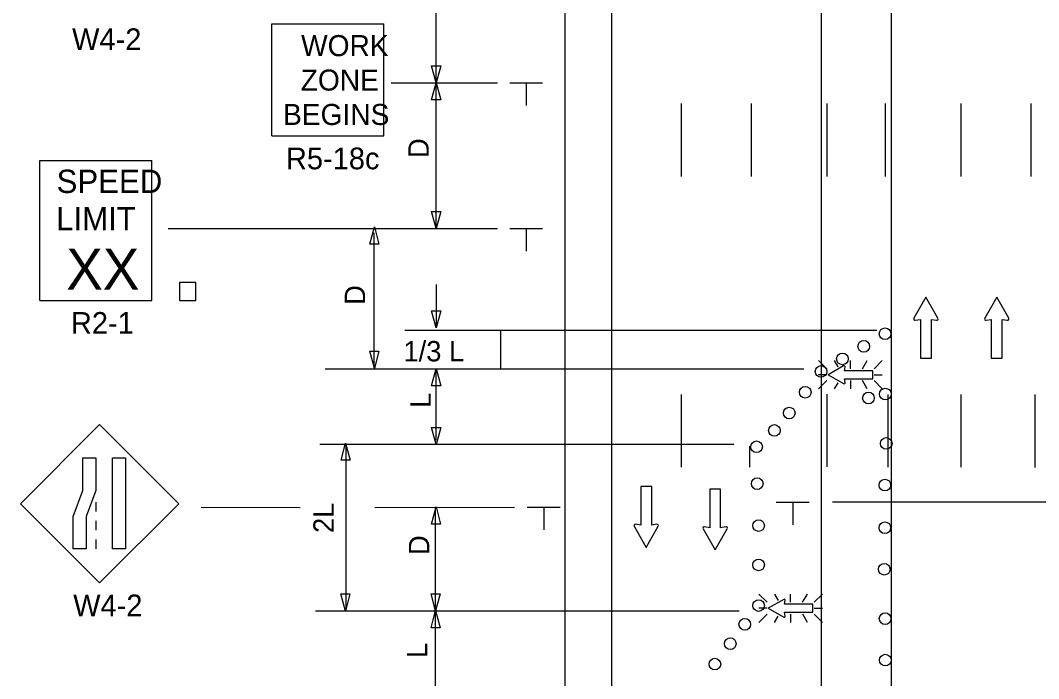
# Model space of a CAD drawing. Extents: x 16646 to 19498, y 2812 to 4437.
# Drawn here: x 16735.8 to 17085.1, y 3563.2 to 3789.1 of the extents above; entities that cross this region are included whole.
import ezdxf

# ---------------------------------------------------------------- set-up
doc = ezdxf.new("R2010")
doc.units = 0
for name, color, linetype in [('ALI_LEGAL_EX', 7, 'Continuous'), ('MT_SCRATCH_LEVEL_E', 7, 'Continuous'), ('PAVT_EDGE_EX', 7, 'Continuous'), ('TRAFFIC_SIGNS_PR', 7, 'Continuous'), ('TYPICAL_EX', 7, 'Continuous'), ('TYPICAL_TEXT_DIMEN_PR', 7, 'Continuous')]:
    doc.layers.add(name, color=color, linetype=linetype)

msp = doc.modelspace()

# ---------------------------------------------------------------- linework, layer by layer
at = {"layer": 'ALI_LEGAL_EX'}
for points in [[(16962.57, 3735.48), (16962.57, 3760.48)], [(16986.57, 3735.48), (16986.57, 3760.48)], [(17012.57, 3735.48), (17012.57, 3760.48)], [(17032.57, 3735.48), (17032.57, 3760.48)], [(17058.57, 3735.48), (17058.57, 3760.48)], [(17082.57, 3735.48), (17082.57, 3760.48)], [(16962.57, 3635.73), (16962.57, 3660.73)], [(17012.57, 3635.86), (17012.57, 3660.86)], [(17033.51, 3635.73), (17033.51, 3660.69)], [(17058.57, 3635.73), (17058.57, 3660.69)], [(17083.89, 3635.68), (17083.89, 3660.68)], [(16986.04, 3635.73), (16986.04, 3642.97)]]:
    msp.add_lwpolyline(points, dxfattribs=at)
at = {"layer": 'MT_SCRATCH_LEVEL_E'}
for p, q in [((17046.44, 3694.1), (17042.33, 3686.86)), ((17046.44, 3694.1), (17042.33, 3686.86)), ((17050.58, 3686.86), (17046.44, 3694.1)), ((17050.58, 3686.86), (17046.44, 3694.1)), ((17070.71, 3694.1), (17066.6, 3686.86)), ((17070.71, 3694.1), (17066.6, 3686.86)), ((17074.85, 3686.86), (17070.71, 3694.1)), ((17074.85, 3686.86), (17070.71, 3694.1)), ((17042.81, 3686.18), (17044.59, 3686.49)), ((17042.81, 3686.18), (17044.59, 3686.49)), ((17044.59, 3686.49), (17044.59, 3673.23)), ((17044.59, 3686.49), (17044.59, 3673.23)), ((17048.33, 3673.23), (17048.33, 3686.49)), ((17048.33, 3686.49), (17050.11, 3686.18)), ((17048.33, 3673.23), (17048.33, 3686.49)), ((17048.33, 3686.49), (17050.11, 3686.18)), ((17067.08, 3686.18), (17068.85, 3686.49)), ((17067.08, 3686.18), (17068.85, 3686.49)), ((17068.85, 3686.49), (17068.85, 3673.23)), ((17068.85, 3686.49), (17068.85, 3673.23)), ((17072.6, 3673.23), (17072.6, 3686.49)), ((17072.6, 3686.49), (17074.38, 3686.18)), ((17072.6, 3673.23), (17072.6, 3686.49)), ((17072.6, 3686.49), (17074.38, 3686.18)), ((17044.59, 3673.23), (17048.33, 3673.23)), ((17044.59, 3673.23), (17048.33, 3673.23)), ((17068.85, 3673.23), (17072.6, 3673.23)), ((17068.85, 3673.23), (17072.6, 3673.23)), ((16952.39, 3629.12), (16948.64, 3629.12)), ((16948.64, 3629.12), (16948.64, 3615.86)), ((16952.39, 3629.12), (16948.64, 3629.12)), ((16948.64, 3629.12), (16948.64, 3615.86)), ((16952.39, 3615.86), (16952.39, 3629.12)), ((16952.39, 3615.86), (16952.39, 3629.12)), ((16976.02, 3628.29), (16972.28, 3628.29)), ((16972.28, 3628.29), (16972.28, 3615.03)), ((16976.02, 3628.29), (16972.28, 3628.29)), ((16972.28, 3628.29), (16972.28, 3615.03)), ((16976.02, 3615.03), (16976.02, 3628.29)), ((16976.02, 3615.03), (16976.02, 3628.29)), ((16946.39, 3615.49), (16950.53, 3608.25)), ((16946.39, 3615.49), (16950.53, 3608.25)), ((16948.64, 3615.86), (16946.87, 3616.18)), ((16948.64, 3615.86), (16946.87, 3616.18)), ((16950.53, 3608.25), (16954.65, 3615.49)), ((16950.53, 3608.25), (16954.65, 3615.49)), ((16954.16, 3616.18), (16952.39, 3615.86)), ((16954.16, 3616.18), (16952.39, 3615.86)), ((16972.28, 3615.03), (16970.5, 3615.35)), ((16972.28, 3615.03), (16970.5, 3615.35)), ((16977.8, 3615.35), (16976.02, 3615.03)), ((16977.8, 3615.35), (16976.02, 3615.03)), ((16970.02, 3614.66), (16974.17, 3607.43)), ((16970.02, 3614.66), (16974.17, 3607.43)), ((16974.17, 3607.43), (16978.28, 3614.66)), ((16974.17, 3607.43), (16978.28, 3614.66))]:
    msp.add_line(p, q, dxfattribs=at)
for centre, start, end in [((17042.73, 3686.63), 150.4248, 279.9638), ((17042.73, 3686.63), 150.4248, 279.9638), ((17050.18, 3686.64), 260.0362, 29.7731), ((17050.18, 3686.64), 260.0362, 29.7731), ((17067, 3686.63), 150.4248, 279.9638), ((17067, 3686.63), 150.4248, 279.9638), ((17074.44, 3686.64), 260.0362, 29.7731), ((17074.44, 3686.64), 260.0362, 29.7731), ((16946.8, 3615.72), 80.0362, 209.7731), ((16946.8, 3615.72), 80.0362, 209.7731), ((16954.24, 3615.72), 330.4248, 99.9638), ((16954.24, 3615.72), 330.4248, 99.9638), ((16970.43, 3614.89), 80.0362, 209.7731), ((16970.43, 3614.89), 80.0362, 209.7731), ((16977.87, 3614.89), 330.4248, 99.9638), ((16977.87, 3614.89), 330.4248, 99.9638)]:
    msp.add_arc(centre, 0.463, start, end, dxfattribs=at)
at = {"layer": 'PAVT_EDGE_EX'}
for p, q in [((16938.57, 3998.47), (16938.57, 3231.86)), ((17010.57, 3998.47), (17010.57, 3554.03)), ((17034.57, 3998.47), (17034.57, 3594.25)), ((16922.57, 3836.4), (16922.57, 3233.74)), ((17010.57, 3836.4), (17010.57, 3563.39)), ((17034.57, 3836.4), (17034.57, 3553.74))]:
    msp.add_line(p, q, dxfattribs=at)
at = {"layer": 'TRAFFIC_SIGNS_PR'}
for p, q in [((16822.13, 3749.41), (16822.13, 3787.81)), ((16822.13, 3787.81), (16860.53, 3787.81)), ((16860.53, 3749.41), (16860.53, 3787.81)), ((16822.13, 3749.41), (16860.53, 3749.41)), ((16742.5, 3740.98), (16780.9, 3740.98)), ((16742.5, 3692.98), (16742.5, 3740.98)), ((16780.9, 3692.98), (16780.9, 3740.98)), ((16742.5, 3692.98), (16780.9, 3692.98)), ((17009.65, 3672.35), (17012.47, 3669.53)), ((17016.37, 3670.16), (17015.11, 3672.35)), ((17020.56, 3669.53), (17020.56, 3672.35)), ((17024.69, 3669.53), (17026.32, 3672.35)), ((17028.64, 3669.53), (17031.46, 3672.35)), ((17012.47, 3667.5), (17009.65, 3667.5)), ((17028.64, 3667.5), (17031.46, 3667.5)), ((17009.65, 3662.65), (17012.47, 3665.47)), ((17015.09, 3662.64), (17016.29, 3664.74)), ((17020.56, 3665.47), (17020.56, 3662.64)), ((17026.34, 3662.64), (17024.72, 3665.47)), ((17028.64, 3665.47), (17031.46, 3662.64)), ((16763, 3650.39), (16735.84, 3623.23)), ((16790.15, 3623.23), (16763, 3650.39)), ((16735.84, 3623.23), (16763, 3596.08)), ((16761.75, 3623.73), (16761.75, 3620.53)), ((16763, 3596.08), (16790.15, 3623.23)), ((16761.75, 3617.33), (16761.75, 3614.13)), ((16761.75, 3610.93), (16761.75, 3607.73)), ((16989.12, 3592.24), (16991.94, 3589.43)), ((16995.84, 3590.06), (16994.58, 3592.25)), ((17000.03, 3589.43), (17000.03, 3592.25)), ((17004.16, 3589.43), (17005.79, 3592.25)), ((17008.11, 3589.43), (17010.93, 3592.25)), ((16991.94, 3587.39), (16989.12, 3587.39)), ((17008.11, 3587.39), (17010.93, 3587.39)), ((16989.12, 3582.54), (16991.94, 3585.36)), ((16994.56, 3582.54), (16995.77, 3584.64)), ((17000.03, 3585.36), (17000.03, 3582.54)), ((17005.82, 3582.54), (17004.19, 3585.36)), ((17008.11, 3585.36), (17010.93, 3582.54))]:
    msp.add_line(p, q, dxfattribs=at)
for points in [[(16790.48, 3692.98), (16796.07, 3692.98), (16796.07, 3699.15), (16790.48, 3699.15)], [(16761.75, 3638.97), (16761.75, 3627.79), (16758.41, 3618.91), (16758.41, 3607.73), (16753.91, 3607.73), (16753.91, 3618.91), (16757.26, 3627.79), (16757.26, 3638.97)], [(16771.89, 3638.97), (16771.89, 3607.73), (16767.39, 3607.73), (16767.39, 3638.97)]]:
    msp.add_lwpolyline(points, close=True, dxfattribs=at)
for points in [[(17018.23, 3670.51), (17012.92, 3667.5), (17018.23, 3664.46)], [(17018.73, 3664.82), (17018.5, 3666.11), (17028.22, 3666.11), (17028.22, 3668.86), (17018.5, 3668.86), (17018.73, 3670.16)], [(16997.7, 3590.41), (16992.39, 3587.39), (16997.7, 3584.35)], [(16998.2, 3584.71), (16997.97, 3586.01), (17007.69, 3586.01), (17007.69, 3588.75), (16997.97, 3588.75), (16998.2, 3590.06)]]:
    msp.add_lwpolyline(points, dxfattribs=at)
for centre in [(17032.45, 3681.54), (17032.45, 3681.54), (17025.13, 3677.23), (17017.8, 3672.92), (17010.47, 3668.61), (17005.05, 3661.48), (17026.74, 3659.51), (17032.51, 3660.87), (16999.56, 3654.35), (16994.47, 3648.37), (16988.36, 3642.77), (17032.81, 3643.91), (16988.57, 3630.13), (17032.38, 3629.64), (16989.06, 3615.74), (16989.06, 3615.74), (17032.38, 3615), (16989.06, 3602.26), (17032.16, 3600.77), (16989.06, 3588.33), (16984.33, 3581.88), (17032.46, 3583.82), (16979.34, 3575.24), (16974.05, 3568.22), (17032.52, 3569.59)]:
    msp.add_circle(centre, 2, dxfattribs=at)
for centre, start, end in [((17018.39, 3670.21), 350.7308, 118.8916), ((17018.39, 3664.76), 241.4833, 9.9593), ((16997.87, 3590.11), 350.7308, 118.8916), ((16997.86, 3584.65), 241.4833, 9.9593)]:
    msp.add_arc(centre, 0.341, start, end, dxfattribs=at)
at = {"layer": 'TYPICAL_EX'}
msp.add_line((16922.57, 3998.47), (16922.57, 3232.23), dxfattribs=at)
at = {"layer": 'TYPICAL_TEXT_DIMEN_PR'}
for p, q in [((16878.47, 3767.62), (16878.47, 3817.62)), ((16878.47, 3767.62), (16876.9, 3773.48)), ((16876.9, 3773.48), (16878.47, 3773.48)), ((16878.47, 3773.48), (16880.04, 3773.48)), ((16880.04, 3773.48), (16878.47, 3767.62)), ((16863.04, 3767.62), (16899.47, 3767.62)), ((16873.47, 3767.62), (16899.47, 3767.62)), ((16876.9, 3761.75), (16878.47, 3767.62)), ((16878.47, 3767.62), (16880.04, 3761.75)), ((16878.47, 3717.62), (16878.47, 3767.62)), ((16903.72, 3767.62), (16914.97, 3767.62)), ((16909.35, 3767.62), (16909.35, 3759.83)), ((16878.47, 3761.75), (16876.9, 3761.75)), ((16880.04, 3761.75), (16878.47, 3761.75)), ((16878.47, 3717.62), (16876.9, 3723.48)), ((16876.9, 3723.48), (16878.47, 3723.48)), ((16878.47, 3723.48), (16880.04, 3723.48)), ((16880.04, 3723.48), (16878.47, 3717.62)), ((16786.55, 3717.62), (16899.47, 3717.62)), ((16855.69, 3712.33), (16857.26, 3718.19)), ((16857.25, 3669.84), (16857.25, 3716.17)), ((16857.26, 3718.19), (16858.83, 3712.33)), ((16903.72, 3717.62), (16914.97, 3717.62)), ((16909.35, 3717.62), (16909.35, 3709.83)), ((16857.26, 3712.33), (16855.69, 3712.33)), ((16858.83, 3712.33), (16857.26, 3712.33)), ((16878.47, 3698.46), (16878.47, 3683.54)), ((16878.47, 3683.54), (16876.9, 3689.4)), ((16876.9, 3689.4), (16878.47, 3689.4)), ((16878.47, 3689.4), (16880.04, 3689.4)), ((16880.04, 3689.4), (16878.47, 3683.54)), ((16867.72, 3682.77), (17029.62, 3682.77)), ((16900.58, 3682.68), (16900.58, 3669.68)), ((16857.26, 3669.72), (16855.69, 3675.59)), ((16855.69, 3675.59), (16857.26, 3675.59)), ((16857.26, 3675.59), (16858.83, 3675.59)), ((16858.83, 3675.59), (16857.26, 3669.72)), ((16840.41, 3669.53), (17004.53, 3669.53)), ((16876.9, 3663.72), (16878.47, 3669.58)), ((16878.47, 3669.58), (16880.04, 3663.72)), ((16878.47, 3645.04), (16878.47, 3669.15)), ((16878.47, 3663.72), (16876.9, 3663.72)), ((16880.04, 3663.72), (16878.47, 3663.72)), ((16878.47, 3643.54), (16876.9, 3649.4)), ((16876.9, 3649.4), (16878.47, 3649.4)), ((16878.47, 3649.4), (16880.04, 3649.4)), ((16880.04, 3649.4), (16878.47, 3643.54)), ((16838.53, 3643.66), (16980.51, 3643.66)), ((16845.85, 3638.13), (16847.42, 3643.99)), ((16847.42, 3643.99), (16848.99, 3638.13)), ((16847.44, 3643.72), (16847.44, 3586.85)), ((16847.42, 3638.13), (16845.85, 3638.13)), ((16848.99, 3638.13), (16847.42, 3638.13)), ((16797.91, 3622.06), (16831.81, 3622)), ((16857.48, 3622.06), (16905.37, 3621.97)), ((16876.86, 3616.28), (16878.43, 3622.15)), ((16878.43, 3622.15), (16880, 3616.28)), ((16909.72, 3622.09), (16920.97, 3622.09)), ((16915.35, 3622.09), (16915.35, 3614.3)), ((16995.13, 3623.76), (17006.38, 3623.76)), ((17000.76, 3623.76), (17000.76, 3615.98)), ((17167.27, 3623.75), (17014.45, 3623.75)), ((16878.26, 3586.43), (16878.26, 3621.73)), ((16878.43, 3616.28), (16876.86, 3616.28)), ((16880, 3616.28), (16878.43, 3616.28)), ((16847.31, 3586.42), (16845.74, 3592.28)), ((16845.74, 3592.28), (16847.31, 3592.28)), ((16847.31, 3592.28), (16848.89, 3592.28)), ((16848.89, 3592.28), (16847.31, 3586.42)), ((16878.28, 3586.52), (16876.71, 3592.38)), ((16876.71, 3592.38), (16878.28, 3592.38)), ((16878.28, 3592.38), (16879.85, 3592.38)), ((16879.85, 3592.38), (16878.28, 3586.52)), ((16837.11, 3586.55), (16982.38, 3586.55)), ((16876.7, 3580.7), (16878.27, 3586.57)), ((16878.26, 3553.86), (16878.26, 3586.14)), ((16878.27, 3586.57), (16879.84, 3580.7)), ((16878.27, 3580.7), (16876.7, 3580.7)), ((16879.84, 3580.7), (16878.27, 3580.7))]:
    msp.add_line(p, q, dxfattribs=at)

# ---------------------------------------------------------------- texts
at = {"layer": 'TRAFFIC_SIGNS_PR'}
for s, height, p in [('W4-2', 7.44, (16753.58, 3778.86)), ('WORK', 7.217, (16832.13, 3776.78)), ('ZONE', 7.217, (16832.01, 3764.97)), ('BEGINS', 7.217, (16825.94, 3753.16)), ('R5-18c', 7.44, (16826.94, 3737.97)), ('SPEED', 8, (16748.27, 3729.84)), ('LIMIT', 8, (16748.11, 3717.04)), ('XX', 14.031, (16751.61, 3696.73)), ('R2-1', 7.44, (16753.18, 3681.54)), ('W4-2', 7.44, (16753.95, 3584.64))]:
    msp.add_text(s, height=height, dxfattribs=at).set_placement(p)
at = {"layer": 'TYPICAL_TEXT_DIMEN_PR'}
for s, p in [('D', (16875.91, 3741.83)), ('D', (16854.09, 3691.45)), ('L', (16876.62, 3656.16)), ('2L', (16843.34, 3613.21)), ('D', (16876.1, 3605.65)), ('L', (16875.42, 3570.3))]:
    msp.add_text(s, height=7, rotation=90, dxfattribs=at).set_placement(p)
msp.add_text('1/3 L', height=7, dxfattribs=at).set_placement((16867.25, 3672.07))

doc.saveas('drawing.dxf')
